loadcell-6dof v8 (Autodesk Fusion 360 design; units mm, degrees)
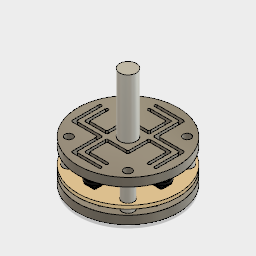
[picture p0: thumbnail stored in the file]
sketch "Sketch1" plane through (0, 0, 0) normal (0, 1, 0) x axis (1, 0, 0)
  line L1 (12.7, 0) -> (0, 0)
  circle C1 centre (0, 0) radius 3.175
  circle C2 centre (12.7, 0) radius 0.8255
  circle C3 centre (0, 12.7) radius 0.8255
  circle C4 centre (-12.7, 0) radius 0.8255
  circle C5 centre (0, -12.7) radius 0.8255
  circle C6 centre (12.7, 0) radius 3.175
  circle C7 centre (0, 12.7) radius 3.175
  circle C8 centre (-12.7, 0) radius 3.175
  circle C9 centre (0, -12.7) radius 3.175
  arc A1 centre (20.7254, 20.7254) radius 19.05 clockwise from (13.8465, 2.9608) to (2.9608, 13.8465)
  arc A2 centre (-20.7254, 20.7254) radius 19.05 clockwise from (-2.9608, 13.8465) to (-13.8465, 2.9608)
  arc A3 centre (-20.7254, -20.7254) radius 19.05 clockwise from (-13.8465, -2.9608) to (-2.9608, -13.8465)
  arc A4 centre (20.7254, -20.7254) radius 19.05 clockwise from (2.9608, -13.8465) to (13.8465, -2.9608)
  point P3 (12.7, 0)
  point P5 (-12.7, 0)
  dimension "d1" diameter C1 = 6.35
  dimension "d2" diameter C2 = 1.651
  dimension "d5" distance P3 P5 = 25.4
  dimension "d6" diameter C6 = 6.35
  dimension "d9" radius A1 = 19.05
  dimension "d4" C-Pattern1-Angle = 360
  dimension "d8" C-Pattern2-Angle = 360
  dimension "d11" C-Pattern3-Angle = 360
extrude "Extrude1" new body sketch "Sketch1" profile of C1 C2 C3 C4 C5 C6 C7 C8 C9 A1 A2 A3 A4 along normal blind 1.5875
extrude "Extrude2" new body sketch "Sketch1" profile of C2 C3 C4 C5 blind 1.651 from offset -0.254
work_plane "WorkPlane1" sketch "Sketch1" AlongDistance -1.27
sketch "Sketch2" plane through (0, -1.27, 0) normal (0, 1, 0) x axis (1, 0, 0)
  line L1 (10.7, -2) -> (14.7, -2)
  line L2 (10.7, 2) -> (10.7, -2)
  line L3 (14.7, 2) -> (10.7, 2)
  line L4 (14.7, -2) -> (14.7, 2)
  line L5 (10.7, 2) -> (14.7, -2)
  line L6 (14.7, 2) -> (10.7, -2)
  line L7 (-2, 14.7) -> (-2, 10.7)
  line L8 (2, 14.7) -> (-2, 14.7)
  line L9 (2, 10.7) -> (2, 14.7)
  line L10 (-2, 10.7) -> (2, 10.7)
  line L11 (-14.7, -2) -> (-10.7, -2)
  line L12 (-14.7, 2) -> (-14.7, -2)
  line L13 (-10.7, 2) -> (-14.7, 2)
  line L14 (-10.7, -2) -> (-10.7, 2)
  line L15 (2, -14.7) -> (2, -10.7)
  line L16 (-2, -14.7) -> (2, -14.7)
  line L17 (-2, -10.7) -> (-2, -14.7)
  line L18 (2, -10.7) -> (-2, -10.7)
  line L19 (0, 0) -> (11.2253, -11.2253)
  line L20 (12.7, 0) -> (0, 0)
  circle C1 centre (0, 0) radius 3.175
  circle C2 centre (0, 0) radius 19.05
  circle C3 centre (11.2253, -11.2253) radius 1.5
  circle C4 centre (11.2253, 11.2253) radius 1.5
  circle C5 centre (-11.2253, 11.2253) radius 1.5
  circle C6 centre (-11.2253, -11.2253) radius 1.5
  circle C7 centre (11.2253, -11.2253) radius 2.25
  circle C8 centre (11.2253, 11.2253) radius 2.25
  circle C9 centre (-11.2253, 11.2253) radius 2.25
  circle C10 centre (-11.2253, -11.2253) radius 2.25
  point P8 (10.7, -2)
  point P9 (10.7, 2)
  point P10 (14.7, 2)
  point P26 (11.2253, -11.2253)
  point P31 (-11.2253, 11.2253)
  dimension "d18" distance P8 P9 = 4
  dimension "d19" distance P9 P10 = 4
  dimension "d22" diameter C2 = 38.1
  dimension "d29" diameter C3 = 3
  dimension "d30" angle L19 L20 = 45
  dimension "d33" distance P26 P31 = 31.75
  dimension "d34" diameter C7 = 4.5
  dimension "d21" C-Pattern1-Angle = 360
  dimension "d32" C-Pattern2-Angle = 360
  dimension "d36" C-Pattern3-Angle = 360
extrude "Extrude3" new body sketch "Sketch2" profile of C1 L1 L2 L3 L4 L7 L8 L9 L10 L11 L12 L13 L14 L15 L16 L17 L18 C2 C3 L20 C4 C5 C6 against normal blind 1.27
extrude "Extrude4" new body sketch "Sketch2" profile of L1 L2 L3 L4 L7 L8 L9 L10 L11 L12 L13 L14 L15 L16 L17 L18 along normal blind 0.508
component_from_bodies "Body->Comp1"
copy_paste_bodies "CutPasteBodies1"
component_from_bodies "Body->Comp2"
copy_paste_bodies "CutPasteBodies1"
offset_faces "OffsetFaces1" distance -0.762
chamfer "Chamfer1" distance 0.254
extrude "Extrude5" sketch "Sketch2" profile of C3 C4 C5 C6 C7 C8 C9 C10 blind -2
extrude "Extrude6" new body sketch "Sketch2" profile of C3 C4 C5 C6 C7 C8 C9 C10 along normal blind 6
sketch "Sketch3" plane through (0, 4.73, 0) normal (0, 1, 0) x axis (-1, 0, 0)
  line L1 (4.7625, 4.7625) -> (-4.7625, 4.7625)
  line L2 (4.7625, -4.7625) -> (4.7625, 4.7625)
  line L3 (-4.7625, -4.7625) -> (4.7625, -4.7625)
  line L4 (-4.7625, 4.7625) -> (-4.7625, -4.7625)
  line L5 (4.7625, -4.7625) -> (-4.7625, 4.7625)
  line L6 (-4.7625, -4.7625) -> (4.7625, 4.7625)
  line L7 (-14.9225, -4.7625) -> (-4.7625, -4.7625)
  line L8 (-14.9225, 5.3975) -> (-14.9225, -4.7625)
  line L9 (-13.3985, 5.3975) -> (-14.9225, 5.3975)
  line L10 (-13.3985, -3.2385) -> (-13.3985, 5.3975)
  line L11 (-4.7625, -3.2385) -> (-13.3985, -3.2385)
  line L12 (-4.7625, 0) -> (0, 0)
  line L13 (-13.3985, 5.3975) -> (-12.3825, 5.3975)
  line L14 (-12.3825, -2.2225) -> (-12.3825, 5.3975)
  line L15 (-4.7625, -2.2225) -> (-12.3825, -2.2225)
  line L16 (-15.9385, -5.7785) -> (-4.7625, -5.7785)
  line L17 (-15.9385, 5.3975) -> (-15.9385, -5.7785)
  line L18 (-15.9385, 5.3975) -> (-14.9225, 5.3975)
  line L19 (-2.2225, -12.3825) -> (5.3975, -12.3825)
  line L20 (-2.2225, -4.7625) -> (-2.2225, -12.3825)
  line L21 (-3.2385, -4.7625) -> (-3.2385, -13.3985)
  line L22 (-3.2385, -13.3985) -> (5.3975, -13.3985)
  line L23 (5.3975, -13.3985) -> (5.3975, -12.3825)
  line L24 (5.3975, -14.9225) -> (-4.7625, -14.9225)
  line L25 (5.3975, -15.9385) -> (-5.7785, -15.9385)
  line L26 (5.3975, -15.9385) -> (5.3975, -14.9225)
  line L27 (-5.7785, -15.9385) -> (-5.7785, -4.7625)
  line L28 (-4.7625, -14.9225) -> (-4.7625, -4.7625)
  line L29 (2.2225, 12.3825) -> (-5.3975, 12.3825)
  line L30 (2.2225, 4.7625) -> (2.2225, 12.3825)
  line L31 (3.2385, 4.7625) -> (3.2385, 13.3985)
  line L32 (3.2385, 13.3985) -> (-5.3975, 13.3985)
  line L33 (-5.3975, 14.9225) -> (4.7625, 14.9225)
  line L34 (-5.3975, 15.9385) -> (5.7785, 15.9385)
  line L35 (-5.3975, 15.9385) -> (-5.3975, 14.9225)
  line L36 (-5.3975, 13.3985) -> (-5.3975, 12.3825)
  line L37 (4.7625, 14.9225) -> (4.7625, 4.7625)
  line L38 (5.7785, 15.9385) -> (5.7785, 4.7625)
  line L39 (15.9385, 5.7785) -> (4.7625, 5.7785)
  line L40 (14.9225, 4.7625) -> (4.7625, 4.7625)
  line L41 (4.7625, 3.2385) -> (13.3985, 3.2385)
  line L42 (4.7625, 2.2225) -> (12.3825, 2.2225)
  line L43 (12.3825, 2.2225) -> (12.3825, -5.3975)
  line L44 (13.3985, 3.2385) -> (13.3985, -5.3975)
  line L45 (13.3985, -5.3975) -> (12.3825, -5.3975)
  line L46 (15.9385, -5.3975) -> (14.9225, -5.3975)
  line L47 (15.9385, -5.3975) -> (15.9385, 5.7785)
  line L48 (14.9225, -5.3975) -> (14.9225, 4.7625)
  line L49 (-5.7785, 5.7785) -> (-5.7785, -5.7785)
  line L50 (5.7785, 5.7785) -> (-5.7785, 5.7785)
  line L51 (5.7785, -5.7785) -> (5.7785, 5.7785)
  line L52 (-5.7785, -5.7785) -> (5.7785, -5.7785)
  circle C1 centre (-11.2253, 11.2253) radius 1.5
  circle C2 centre (-11.2253, 11.2253) radius 2.25
  circle C3 centre (-11.2253, -11.2253) radius 1.5
  circle C4 centre (11.2253, -11.2253) radius 1.5
  circle C5 centre (11.2253, 11.2253) radius 1.5
  circle C6 centre (-11.2253, 11.2253) radius 1.5
  circle C7 centre (0, 0) radius 19.05
  circle C8 centre (0, 0) radius 3.175
  point P9 (-4.7625, 4.7625)
  point P12 (-4.7625, -4.7625)
  point P10 (4.7625, 4.7625)
  point P14 (-14.9225, -4.7625)
  point P15 (-14.9225, 5.3975)
  dimension "d42" distance P9 P12 = 9.525
  dimension "d43" distance P9 P10 = 9.525
  dimension "d44" distance L8 L10 = 1.524
  dimension "d45" distance L7 L11 = 1.524
  dimension "d46" distance P12 P14 = 10.16
  dimension "d47" distance P14 P15 = 10.16
  dimension "d49" = 1.016
  dimension "d50" = 1.016
  dimension "d51" = 1.016
extrude "Extrude7" sketch "Sketch3" profile of C1 C2 C3 C4 C5 C6 C7 C8 L1 L2 L3 L4 L7 L8 L9 L10 L11 L15 L14 L13 L17 L16 L18 L19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 blind 3.175
component_from_bodies "Body->Comp3"
fillet "Fillet1" radius 0.508
base_feature "Base Feature1"
fillet "Fillet1" radius 0.508 named "d54_1"
position "Position1"
sketch "Sketch4" plane through (0, -7.715, 0) normal (0, -1, 0) x axis (1, 0, 0)
  line L1 (5.2705, 5.7785) -> (-1.7145, 5.7785)
  line L2 (5.7785, -1.7145) -> (5.7785, 5.2705)
  line L3 (11.8745, -2.2225) -> (6.2865, -2.2225)
  line L4 (12.3825, 4.8895) -> (12.3825, -1.7145)
  line L5 (13.3985, -2.7305) -> (13.3985, 4.8895)
  line L6 (5.2705, -3.2385) -> (12.8905, -3.2385)
  line L7 (4.7625, 4.2545) -> (4.7625, -2.7305)
  line L8 (-2.7305, 4.7625) -> (4.2545, 4.7625)
  line L9 (-3.2385, 12.8905) -> (-3.2385, 5.2705)
  line L10 (4.8895, 13.3985) -> (-2.7305, 13.3985)
  line L11 (-2.2225, 12.3825) -> (4.8895, 12.3825)
  line L12 (-2.2225, 6.2865) -> (-2.2225, 12.3825)
  line L13 (5.7785, -15.4305) -> (5.7785, -6.2865)
  line L14 (-4.8895, -15.9385) -> (5.2705, -15.9385)
  line L15 (4.2545, -14.9225) -> (-4.8895, -14.9225)
  line L16 (4.7625, -5.2705) -> (4.7625, -14.4145)
  line L17 (14.4145, -4.7625) -> (5.2705, -4.7625)
  line L18 (14.9225, 4.8895) -> (14.9225, -4.2545)
  line L19 (15.9385, -5.2705) -> (15.9385, 4.8895)
  line L20 (6.2865, -5.7785) -> (15.4305, -5.7785)
  line L21 (-14.9225, -4.8895) -> (-14.9225, 4.2545)
  line L22 (-15.9385, 5.2705) -> (-15.9385, -4.8895)
  line L23 (-6.2865, 5.7785) -> (-15.4305, 5.7785)
  line L24 (-5.7785, 15.4305) -> (-5.7785, 6.2865)
  line L25 (4.8895, 15.9385) -> (-5.2705, 15.9385)
  line L26 (-4.2545, 14.9225) -> (4.8895, 14.9225)
  line L27 (-4.7625, 5.2705) -> (-4.7625, 14.4145)
  line L28 (-14.4145, 4.7625) -> (-5.2705, 4.7625)
  line L29 (-12.3825, 2.2225) -> (-6.2865, 2.2225)
  line L30 (-12.3825, -4.8895) -> (-12.3825, 2.2225)
  line L31 (-13.3985, 2.7305) -> (-13.3985, -4.8895)
  line L32 (-5.2705, 3.2385) -> (-12.8905, 3.2385)
  line L33 (-4.7625, -4.2545) -> (-4.7625, 2.7305)
  line L34 (2.7305, -4.7625) -> (-4.2545, -4.7625)
  line L35 (3.2385, -13.3985) -> (3.2385, -5.2705)
  line L36 (-4.8895, -13.3985) -> (3.2385, -13.3985)
  line L37 (1.7145, -12.3825) -> (-4.8895, -12.3825)
  line L38 (2.2225, -6.2865) -> (2.2225, -11.8745)
  line L39 (-5.2705, -5.7785) -> (1.7145, -5.7785)
  line L40 (-5.7785, 1.7145) -> (-5.7785, -5.2705)
  arc A1 centre (-1.7145, 6.2865) radius 0.508 clockwise from (-1.7145, 5.7785) to (-2.2225, 6.2865)
  arc A2 centre (5.2705, 5.2705) radius 0.508 clockwise from (5.2705, 5.7785) to (5.7785, 5.2705)
  arc A3 centre (6.2865, -1.7145) radius 0.508 clockwise from (6.2865, -2.2225) to (5.7785, -1.7145)
  arc A4 centre (11.8745, -1.7145) radius 0.508 clockwise from (12.3825, -1.7145) to (11.8745, -2.2225)
  arc A5 centre (12.8905, 4.8895) radius 0.508 clockwise from (12.3825, 4.8895) to (13.3985, 4.8895)
  arc A6 centre (12.8905, -2.7305) radius 0.508 clockwise from (13.3985, -2.7305) to (12.8905, -3.2385)
  arc A7 centre (5.2705, -2.7305) radius 0.508 clockwise from (5.2705, -3.2385) to (4.7625, -2.7305)
  arc A8 centre (4.2545, 4.2545) radius 0.508 clockwise from (4.2545, 4.7625) to (4.7625, 4.2545)
  arc A9 centre (-2.7305, 5.2705) radius 0.508 clockwise from (-2.7305, 4.7625) to (-3.2385, 5.2705)
  arc A10 centre (-2.7305, 12.8905) radius 0.508 clockwise from (-3.2385, 12.8905) to (-2.7305, 13.3985)
  arc A11 centre (4.8895, 12.8905) radius 0.508 clockwise from (4.8895, 13.3985) to (4.8895, 12.3825)
  arc A12 centre (6.2865, -6.2865) radius 0.508 clockwise from (5.7785, -6.2865) to (6.2865, -5.7785)
  arc A13 centre (5.2705, -15.4305) radius 0.508 clockwise from (5.7785, -15.4305) to (5.2705, -15.9385)
  arc A14 centre (-4.8895, -15.4305) radius 0.508 clockwise from (-4.8895, -15.9385) to (-4.8895, -14.9225)
  arc A15 centre (4.2545, -14.4145) radius 0.508 clockwise from (4.7625, -14.4145) to (4.2545, -14.9225)
  arc A16 centre (5.2705, -5.2705) radius 0.508 clockwise from (4.7625, -5.2705) to (5.2705, -4.7625)
  arc A17 centre (14.4145, -4.2545) radius 0.508 clockwise from (14.9225, -4.2545) to (14.4145, -4.7625)
  arc A18 centre (15.4305, 4.8895) radius 0.508 clockwise from (14.9225, 4.8895) to (15.9385, 4.8895)
  arc A19 centre (15.4305, -5.2705) radius 0.508 clockwise from (15.9385, -5.2705) to (15.4305, -5.7785)
  circle C1 centre (-11.2253, -11.2253) radius 1.5
  circle C2 centre (-11.2253, 11.2253) radius 1.5
  circle C3 centre (11.2253, -11.2253) radius 1.5
  circle C4 centre (11.2253, 11.2253) radius 1.5
  circle C5 centre (0, 0) radius 3.175
  circle C6 centre (0, 0) radius 19.05
  arc A20 centre (-14.4145, 4.2545) radius 0.508 clockwise from (-14.9225, 4.2545) to (-14.4145, 4.7625)
  arc A21 centre (-15.4305, -4.8895) radius 0.508 clockwise from (-14.9225, -4.8895) to (-15.9385, -4.8895)
  arc A22 centre (-15.4305, 5.2705) radius 0.508 clockwise from (-15.9385, 5.2705) to (-15.4305, 5.7785)
  arc A23 centre (-6.2865, 6.2865) radius 0.508 clockwise from (-5.7785, 6.2865) to (-6.2865, 5.7785)
  arc A24 centre (-5.2705, 15.4305) radius 0.508 clockwise from (-5.7785, 15.4305) to (-5.2705, 15.9385)
  arc A25 centre (4.8895, 15.4305) radius 0.508 clockwise from (4.8895, 15.9385) to (4.8895, 14.9225)
  arc A26 centre (-4.2545, 14.4145) radius 0.508 clockwise from (-4.7625, 14.4145) to (-4.2545, 14.9225)
  arc A27 centre (-5.2705, 5.2705) radius 0.508 clockwise from (-4.7625, 5.2705) to (-5.2705, 4.7625)
  arc A28 centre (-6.2865, 1.7145) radius 0.508 clockwise from (-6.2865, 2.2225) to (-5.7785, 1.7145)
  arc A29 centre (-12.8905, -4.8895) radius 0.508 clockwise from (-12.3825, -4.8895) to (-13.3985, -4.8895)
  arc A30 centre (-12.8905, 2.7305) radius 0.508 clockwise from (-13.3985, 2.7305) to (-12.8905, 3.2385)
  arc A31 centre (-5.2705, 2.7305) radius 0.508 clockwise from (-5.2705, 3.2385) to (-4.7625, 2.7305)
  arc A32 centre (-4.2545, -4.2545) radius 0.508 clockwise from (-4.2545, -4.7625) to (-4.7625, -4.2545)
  arc A33 centre (2.7305, -5.2705) radius 0.508 clockwise from (2.7305, -4.7625) to (3.2385, -5.2705)
  arc A34 centre (-4.8895, -12.8905) radius 0.508 clockwise from (-4.8895, -13.3985) to (-4.8895, -12.3825)
  arc A35 centre (1.7145, -11.8745) radius 0.508 clockwise from (2.2225, -11.8745) to (1.7145, -12.3825)
  arc A36 centre (1.7145, -6.2865) radius 0.508 clockwise from (1.7145, -5.7785) to (2.2225, -6.2865)
  arc A37 centre (-5.2705, -5.2705) radius 0.508 clockwise from (-5.2705, -5.7785) to (-5.7785, -5.2705)
  circle C7 centre (0, 0) radius 3.175
extrude "Extrude8" sketch "Sketch4" profile of C5 C7 blind 1.27 second side blind 38.1
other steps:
base_feature "Base Feature1"
base_feature "Base Feature1"
base_feature "Base Feature2"
base_feature "Base Feature1"
base_feature "Base Feature2"
create_component "CreateComponent1"
remove_body "RemoveBody1"
remove_body "RemoveBody2"
remove_body "RemoveBody3"
remove_body "RemoveBody4"
remove_body "RemoveBody5"
create_component "CreateComponent2"
remove_body "RemoveBody6"
remove_body "RemoveBody7"
remove_body "RemoveBody8"
remove_body "RemoveBody9"
remove_body "RemoveBody10"
create_component "CreateComponent3"
remove_body "RemoveBody11"
create_component "CreateComponent4"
